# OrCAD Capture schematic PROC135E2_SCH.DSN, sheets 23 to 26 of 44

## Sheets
23 23. CPSW RGMII_2 ETHERNET CONN.: size C; title: CPSW RMII_2 ETHERNET PHY
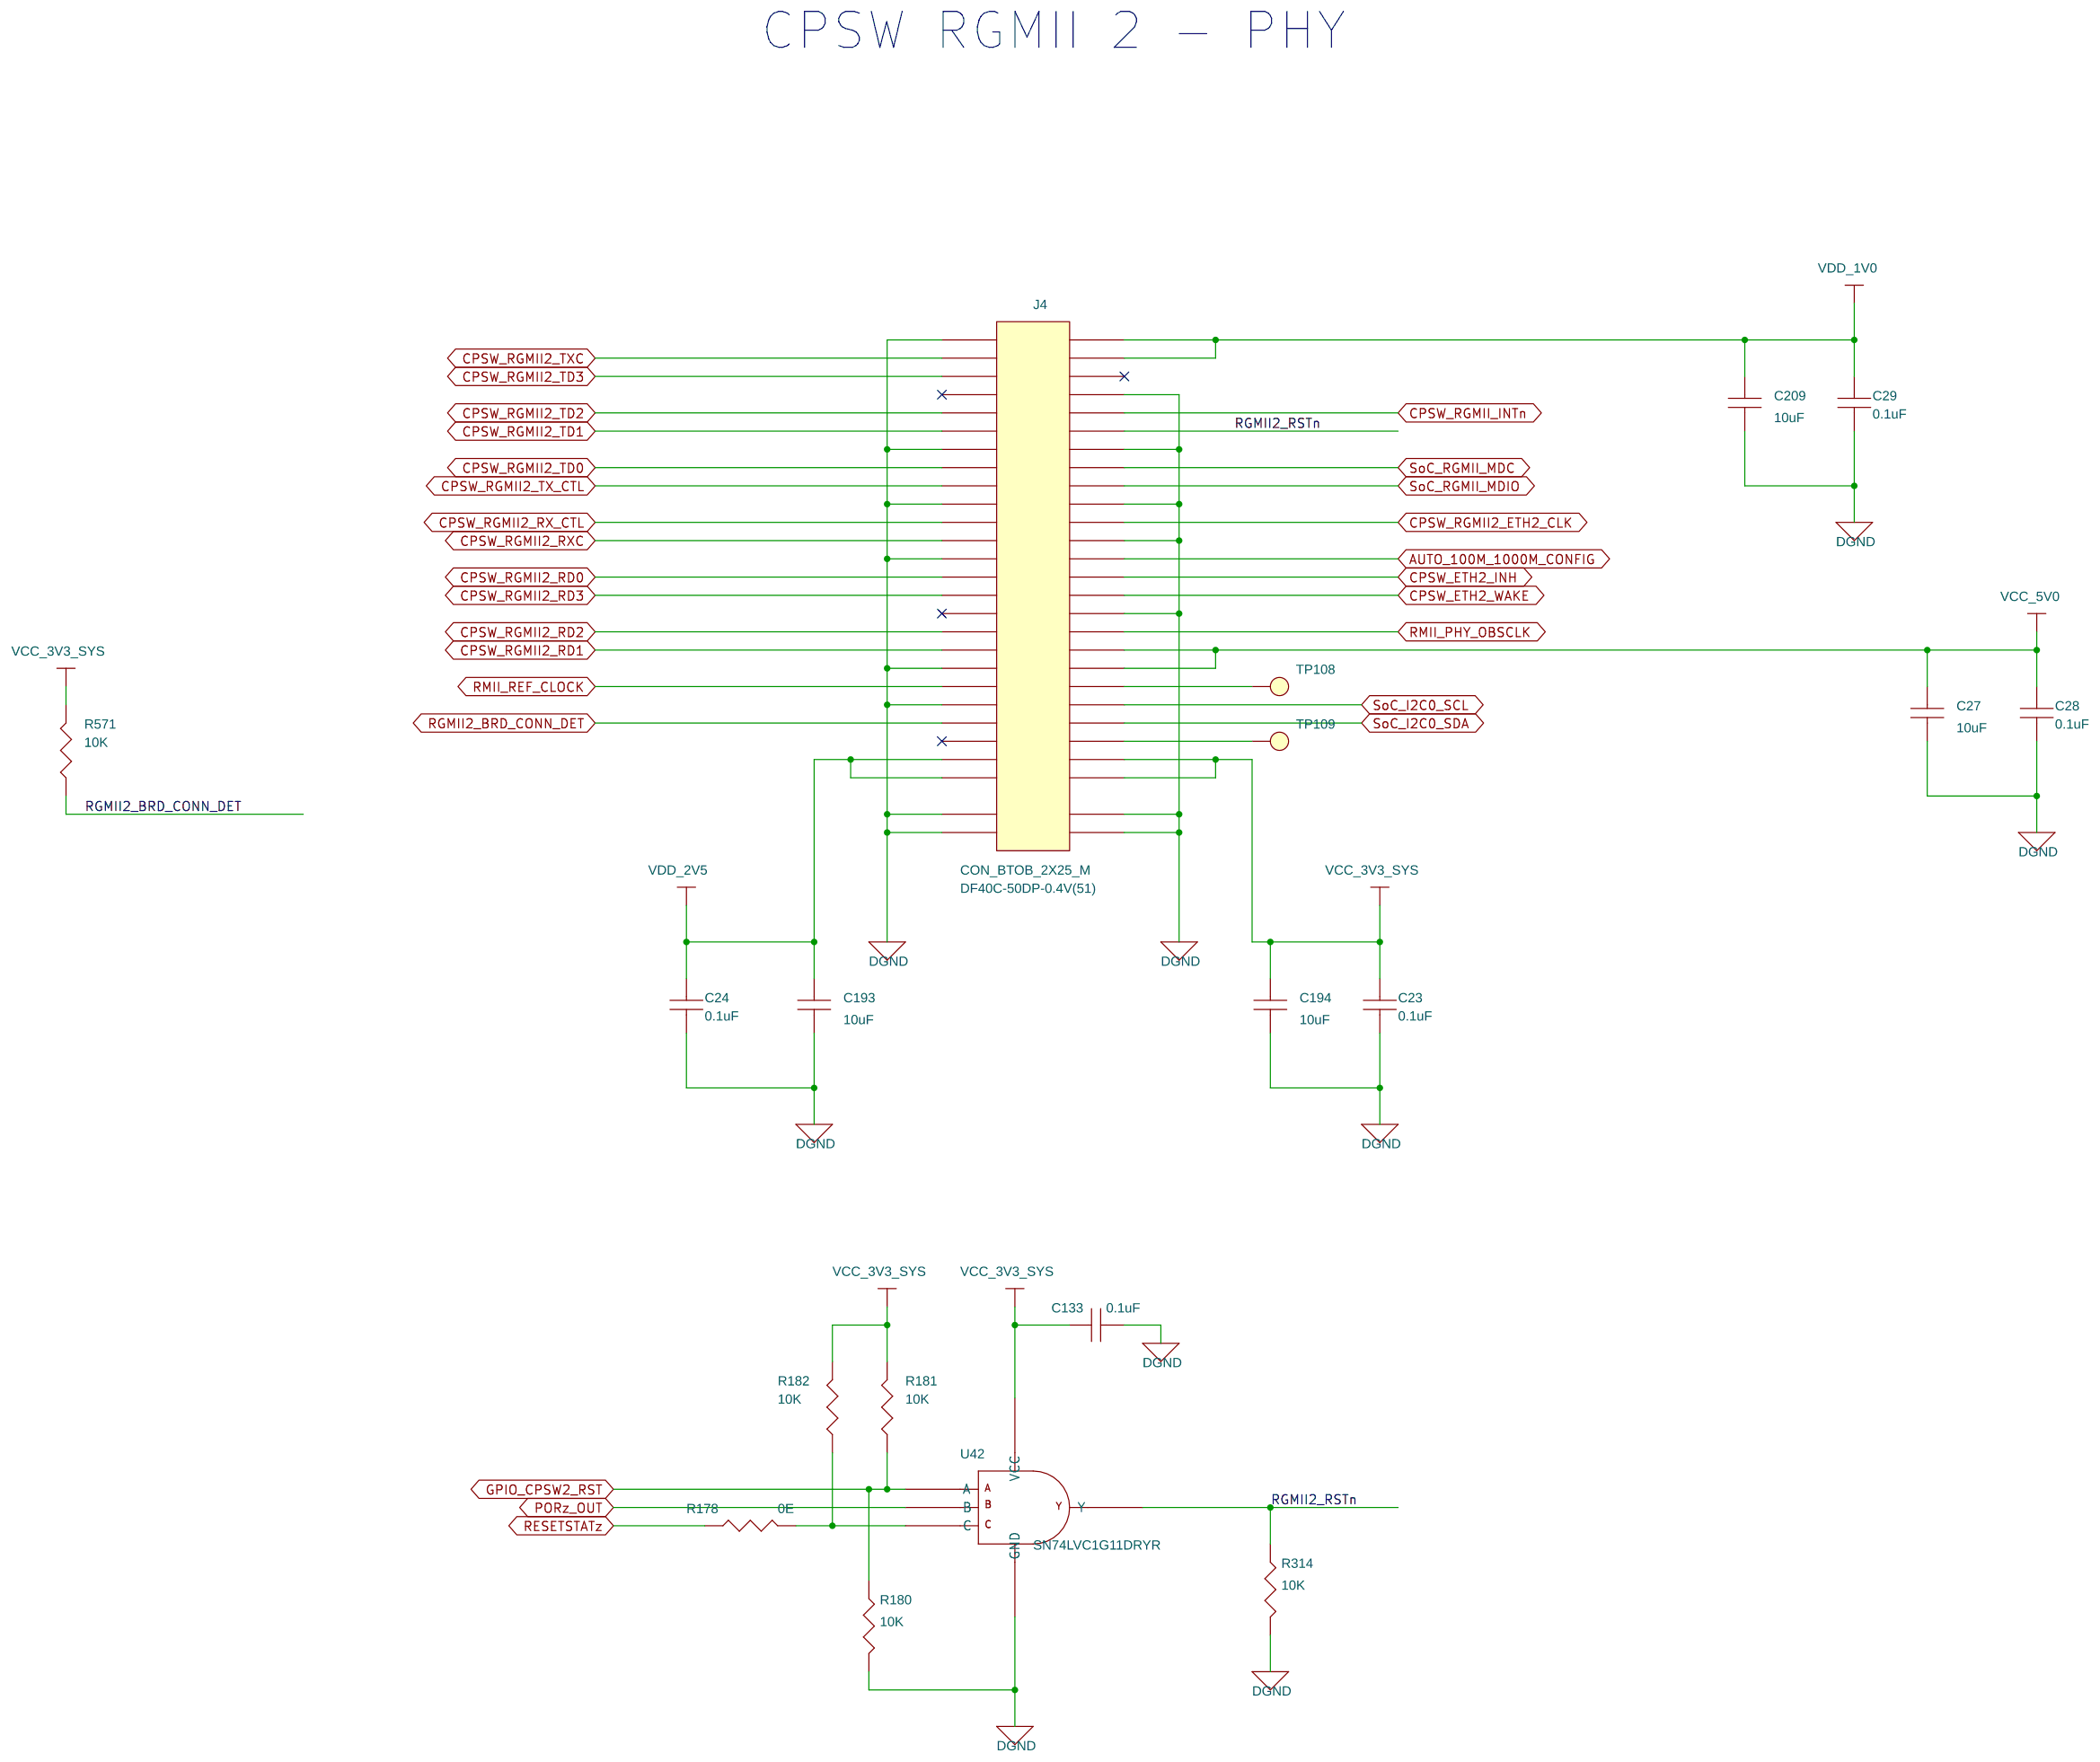
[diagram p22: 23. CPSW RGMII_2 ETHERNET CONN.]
24 24. PHY CLK & LED DRIVER: size C; title: ETHERNET PHY CLOCK BUFFER & LED DRIVER
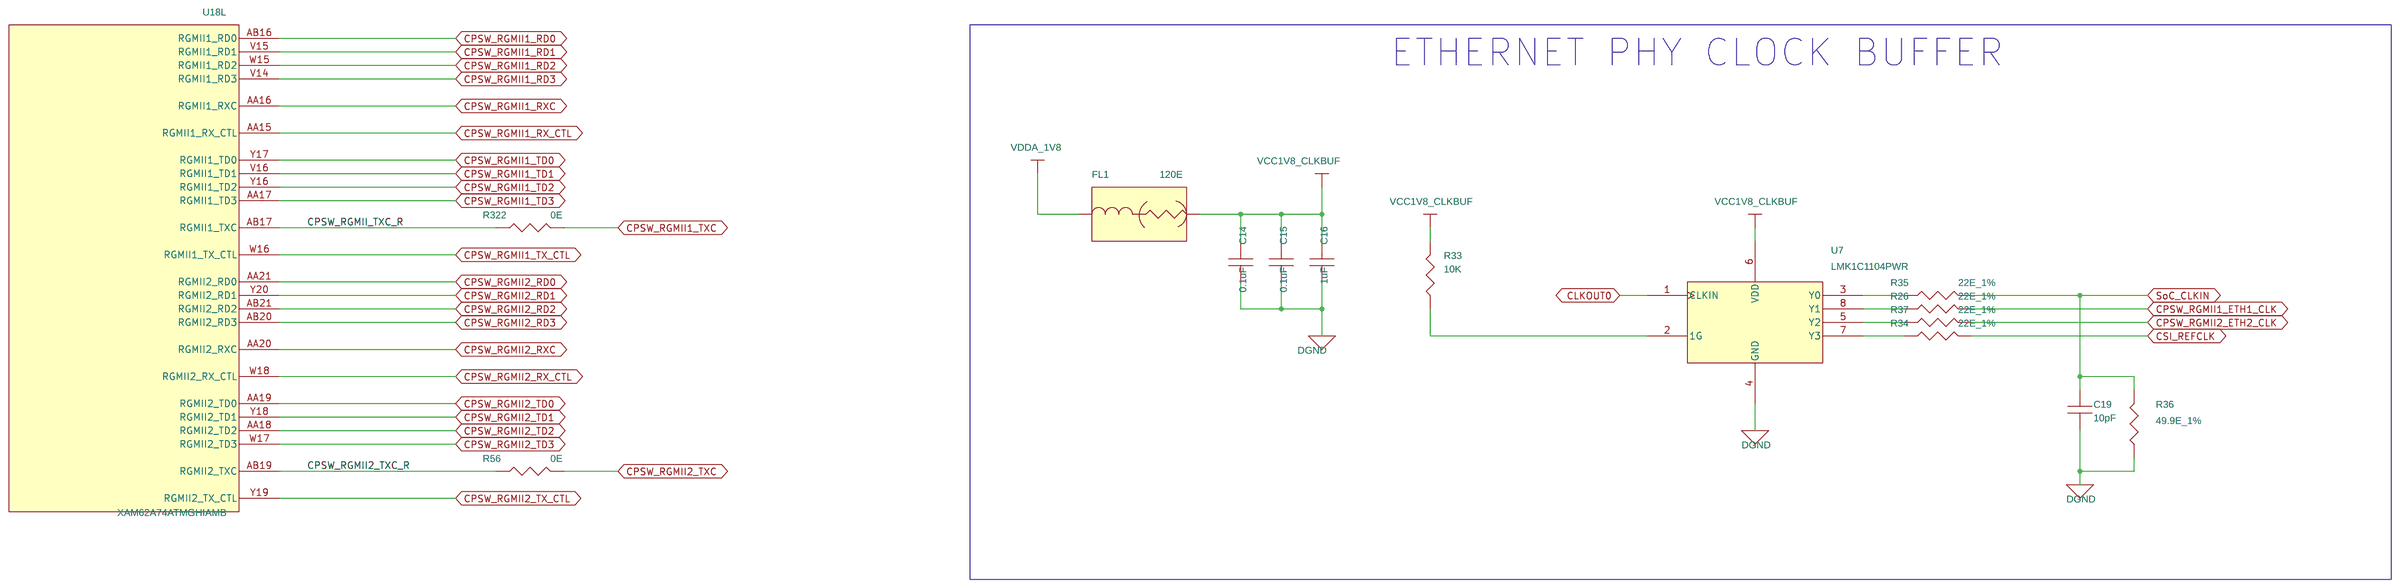
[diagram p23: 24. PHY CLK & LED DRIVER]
25 25. TEST AUTOMATION: size C; title: TEST AUTOMATION
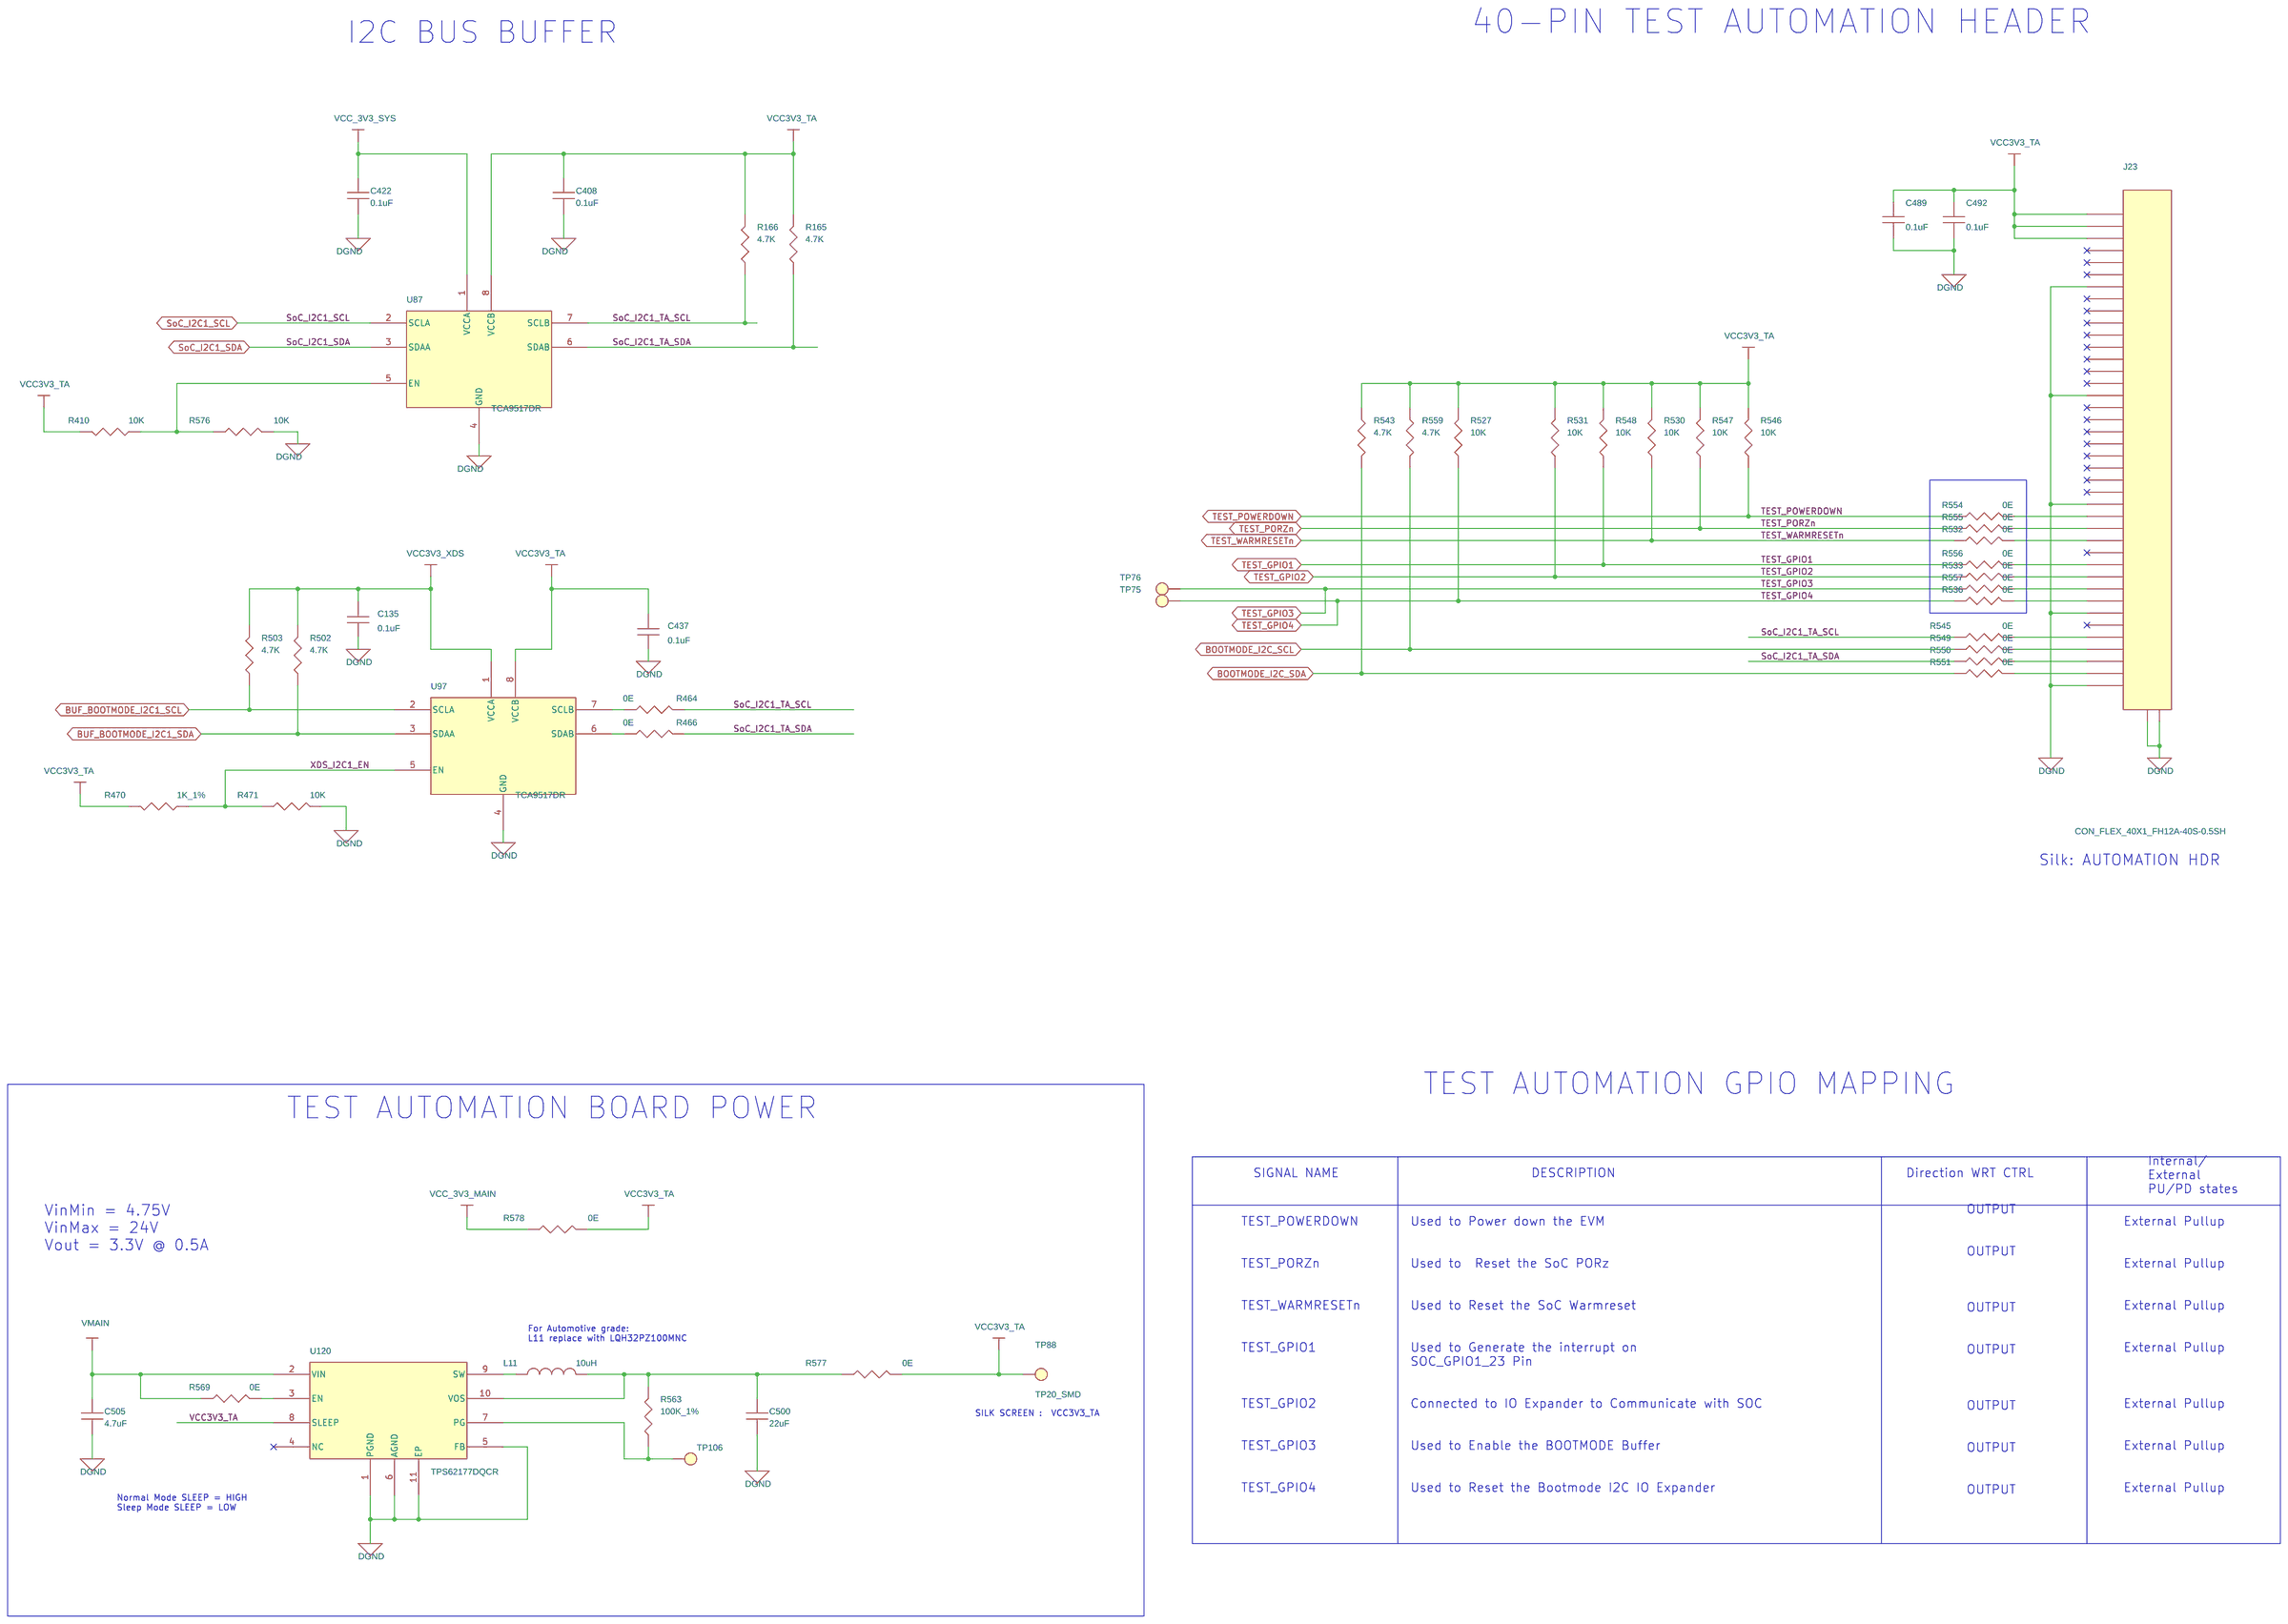
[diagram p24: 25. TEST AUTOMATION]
26 26. BOOT MODE BUFFER & SWITCHES: size C; title: BOOT MODE BUFFER & SWITCHES
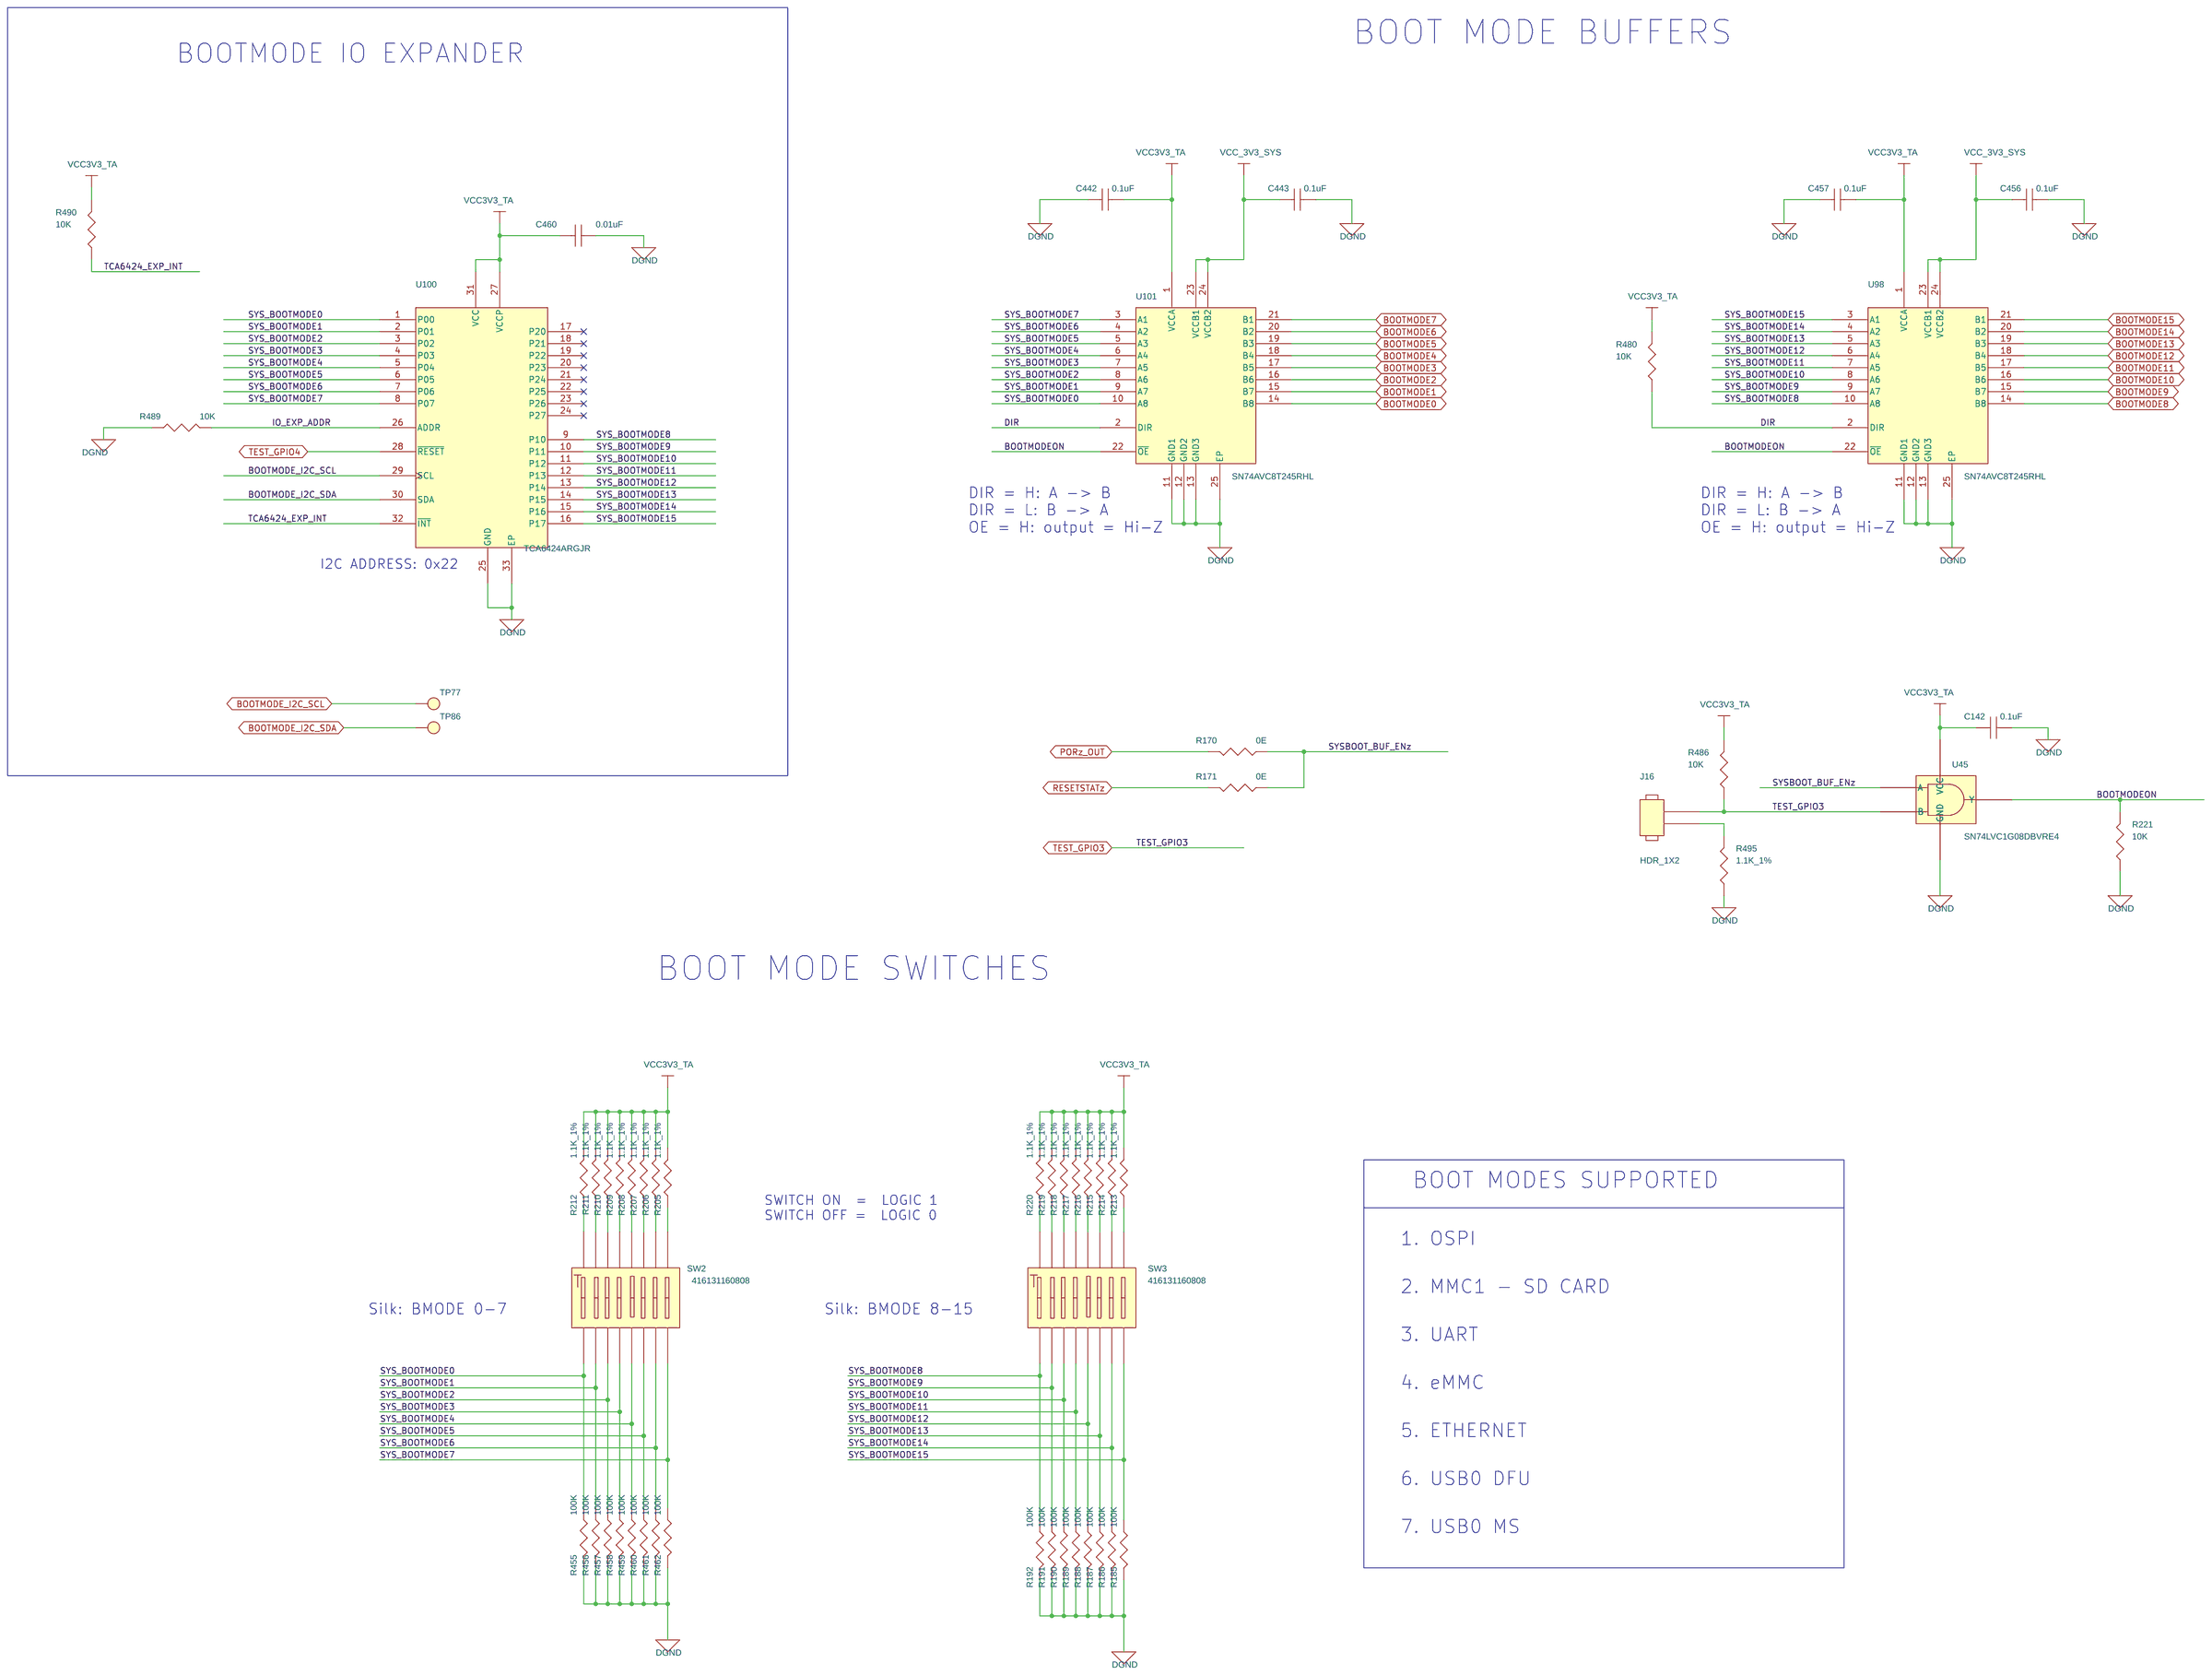
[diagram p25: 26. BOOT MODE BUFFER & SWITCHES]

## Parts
sheet 23. CPSW RGMII_2 ETHERNET CONN.
C23  0.1uF  [CAP0402_0-75]
C24  0.1uF  [CAP0402_0-75]
C27  10uF  [CAP0402_0-75]
C28  0.1uF  [CAP0402_0-75]
C29  0.1uF  [CAP0402_0-75]
C133  0.1uF  [CAP0201_0-5]
C193  10uF  [CAP0402_0-75]
C194  10uF  [CAP0402_0-75]
C209  10uF  [CAP0402_0-75]
J4  CON_BTOB_2X25_M  [CON_BTOB2X25_DF40C-50DP_P_S_S_1-3]
R178  0E  [RES0201_0-5]
R180  10K  [RES0201_0-5]
R181  10K  [RES0201_0-5]
R182  10K  [RES0201_0-5]
R314  10K  [RES0201_0-5]
R571  10K  [RES0201_0-5]
TP108  TP30_SMD  [TP30_SMD]
TP109  TP30_SMD  [TP30_SMD]
U42  SN74LVC1G11DRYR  [SON6_SN74LVC2G17_40X60_0-6]
sheet 24. PHY CLK & LED DRIVER
C14  0.1uF  [CAP0201_0-5]
C15  0.1uF  [CAP0201_0-5]
C16  1uF  [CAP0201_0-5]
C19  10pF  [CAP0201_0-5]
FL1  120E  [EMIFIL_BLM15A_0402_0-6]
R26  22E_1%  [RES0201_0-5]
R33  10K  [RES0201_0-5]
R34  22E_1%  [RES0201_0-5]
R35  22E_1%  [RES0201_0-5]
R36  49.9E_1%  [RES0402_0-5]
R37  22E_1%  [RES0201_0-5]
R56  0E  [RES0201_0-5]
R322  0E  [RES0201_0-5]
U7  LMK1C1104PWR  [TSSOP8_25-59_125X180_1-2]
sheet 25. TEST AUTOMATION
C135  0.1uF  [CAP0201_0-5]
C408  0.1uF  [CAP0201_0-5]
C422  0.1uF  [CAP0201_0-5]
C437  0.1uF  [CAP0201_0-5]
C489  0.1uF  [CAP0201_0-5]
C492  0.1uF  [CAP0201_0-5]
C500  22uF  [CAP0603_1]
C505  4.7uF  [CAP0603_1]
J23  CON_FLEX_40X1_FH12A-40S-0.5SH  [CON_FLEX40X1_FH12A_S_R_S]
L11  10uH  [IND_1277AS-H_130X110_SMD_1-2]
R165  4.7K  [RES0201_0-5]
R166  4.7K  [RES0201_0-5]
R410  10K  [RES0201_0-5]
R464  0E  [RES0201_0-5]
R466  0E  [RES0201_0-5]
R470  1K_1%  [RES0402_0-5]
R471  10K  [RES0201_0-5]
R502  4.7K  [RES0201_0-5]
R503  4.7K  [RES0201_0-5]
R527  10K  [RES0201_0-5]
R530  10K  [RES0201_0-5]
R531  10K  [RES0201_0-5]
R532  0E  [RES0201_0-5]
R533  0E  [RES0201_0-5]
R536  0E  [RES0201_0-5]
R543  4.7K  [RES0201_0-5]
R545  0E  [RES0201_0-5]
R546  10K  [RES0201_0-5]
R547  10K  [RES0201_0-5]
R548  10K  [RES0201_0-5]
R549  0E  [RES0201_0-5]
R550  0E  [RES0201_0-5]
R551  0E  [RES0201_0-5]
R554  0E  [RES0201_0-5]
R555  0E  [RES0201_0-5]
R556  0E  [RES0201_0-5]
R557  0E  [RES0201_0-5]
R559  4.7K  [RES0201_0-5]
R563  100K_1%  [RES0402_0-5]
R569  0E  [RES0402_0-5]
R576  10K  [RES0201_0-5]
R577  0E  [RES0805_0-75]
R578  0E  [RES0805_0-75]
TP75  TP20_SMD  [TP20_SMD]
TP76  TP20_SMD  [TP20_SMD]
TP88  TP20_SMD  [TP20_SMD]
TP106  TP20_SMD  [TP20_SMD]
U87  TCA9517DR  [SOIC8_1-8]
U97  TCA9517DR  [SOIC8_1-8]
U120  TPS62177DQCR  [WSON10_19-68_80X120_0-8]
sheet 26. BOOT MODE BUFFER & SWITCHES
C142  0.1uF  [CAP0201_0-5]
C442  0.1uF  [CAP0201_0-5]
C443  0.1uF  [CAP0201_0-5]
C456  0.1uF  [CAP0201_0-5]
C457  0.1uF  [CAP0201_0-5]
C460  0.01uF  [CAP0201_0-5]
J16  HDR_1X2  [HDR_1X2_90120-0122_S_T_5-6]
R170  0E  [RES0201_0-5]
R171  0E  [RES0201_0-5]
R185  100K  [RES0201_0-5]
R186  100K  [RES0201_0-5]
R187  100K  [RES0201_0-5]
R188  100K  [RES0201_0-5]
R189  100K  [RES0201_0-5]
R190  100K  [RES0201_0-5]
R191  100K  [RES0201_0-5]
R192  100K  [RES0201_0-5]
R205  1.1K_1%  [RES0201_0-5]
R206  1.1K_1%  [RES0201_0-5]
R207  1.1K_1%  [RES0201_0-5]
R208  1.1K_1%  [RES0201_0-5]
R209  1.1K_1%  [RES0201_0-5]
R210  1.1K_1%  [RES0201_0-5]
R211  1.1K_1%  [RES0201_0-5]
R212  1.1K_1%  [RES0201_0-5]
R213  1.1K_1%  [RES0201_0-5]
R214  1.1K_1%  [RES0201_0-5]
R215  1.1K_1%  [RES0201_0-5]
R216  1.1K_1%  [RES0201_0-5]
R217  1.1K_1%  [RES0201_0-5]
R218  1.1K_1%  [RES0201_0-5]
R219  1.1K_1%  [RES0201_0-5]
R220  1.1K_1%  [RES0201_0-5]
R221  10K  [RES0201_0-5]
R455  100K  [RES0201_0-5]
R456  100K  [RES0201_0-5]
R457  100K  [RES0201_0-5]
R458  100K  [RES0201_0-5]
R459  100K  [RES0201_0-5]
R460  100K  [RES0201_0-5]
R461  100K  [RES0201_0-5]
R462  100K  [RES0201_0-5]
R480  10K  [RES0201_0-5]
R486  10K  [RES0201_0-5]
R489  10K  [RES0201_0-5]
R490  10K  [RES0201_0-5]
R495  1.1K_1%  [RES0201_0-5]
SW2  416131160808  [SW16_416131160808_460X230_SMD_2-7]
SW3  416131160808  [SW16_416131160808_460X230_SMD_2-7]
TP77  TP20_SMD  [TP20_SMD]
TP86  TP20_SMD  [TP20_SMD]
U45  SN74LVC1G08DBVRE4  [SOT23-5]
U98  SN74AVC8T245RHL  [QFN24_19-68_220X140_1]
U100  TCA6424ARGJR  [QFN32_19-68_200X200]
U101  SN74AVC8T245RHL  [QFN24_19-68_220X140_1]
sheet 31. SOC WKUP & GPMC
U18  XAM62A74ATMGHIAMB  [FBGA484_31-49_710X710_2-7]  (sections A,B,C,D,E,F,G,H,I,J,K,L,M,N,O,P,Q)

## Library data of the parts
C23 C24 C28 C29 = CAP: CAP CERAMIC 0.1uF 50V 10% X7R 0402; Chkd/date: MANIRAJA/261020; Crtd /date: ALVY/211020; Custom_Duty: 15%; Customs_HS_Code: 85322990; Distributor_name: DIGIKEY; Distributor_part_number: 490-10700-1-ND; Footprint Path: Y:\MIS_DATABASE\Library\ALTIUM_TOOL\PCB_FOOTPRINTS\Altium_Footprint_Lib.PcbLib; Height: 0.55MM; Library Path: Y:\MIS_DATABASE\Library\ALTIUM_TOOL\SCHEMATICS_PARTS\MS_DISCRETE_Library.schlib; Mfr_name: MURATA; Mfr_part_number: GRM155R71H104KE14D; Mistral Part No: 120011100014-R; Package: 0402; Part_type: CAPACITORS\CERAMIC; Project: J7_CP; RoHS: RoHS; Temperature: -55°C+125°C; Tolerance: 10%; Voltage: 50V; Wattage: NA; Weight: 3.1mg; Datasheet: Y:\MIS_DATABASE\DATASHEETS\CAPACITORS\GRM155R71H104KE14.PDF
C27 C193 C194 C209 = CAP: CAP CERAMIC 10uF 10V 20% X5R 0402; Chkd/date: MANIRAJA/300520; Crtd /date: ALVY/260520; Custom_Duty: 15%; Customs_HS_Code: 85322990; Distributor_name: DIGIKEY; Distributor_part_number: 490-GRM155R61A106ME11DTR-ND; Footprint Path: Y:\MIS_DATABASE\Library\ALTIUM_TOOL\PCB_FOOTPRINTS\Altium_Footprint_Lib.PcbLib; Height: 0.55MM; Library Path: Y:\MIS_DATABASE\Library\ALTIUM_TOOL\SCHEMATICS_PARTS\MS_DISCRETE_Library.schlib; Mfr_name: MURATA; Mfr_part_number: GRM155R61A106ME11D; Mistral Part No: 120013110019-R; Package: 0402; Part_type: CAPACITORS\CERAMIC; Project: QCS610_NANOSOM; RoHS: RoHS; Temperature: -55°C+85°C; Tolerance: 20%; Voltage: 10V; Wattage: NA; Weight: 3.1mg; Datasheet: Y:\MIS_DATABASE\DATASHEETS\CAPACITORS\MURATA-GXX-SER_NOV17.PDF
C14 C15 C133 C135 C142 C408 C422 C437 C442 C443 C456 C457 C489 C492 = CAP: CAP CERAMIC 0.1uF 16V 10% X5R 0201; Alt_Mfr_name: YAGEO AMERICA; Alt_Mfr_part_number: CC0402KRX5R8BB104; Chkd/date: MANIRAJA/230118; Crtd /date: MANIRAJA/230118; Custom_Duty: 15%; Customs_HS_Code: 85322990; Distributor_name: DIGIKEY; Distributor_part_number: 490-14305-1-ND; Footprint Path: Y:\MIS_DATABASE\Library\ALTIUM_TOOL\PCB_FOOTPRINTS\Altium_Footprint_Lib.PcbLib; Height: 0.33MM; Library Path: Y:\MIS_DATABASE\Library\ALTIUM_TOOL\SCHEMATICS_PARTS\MS_DISCRETE_Library.schlib; Mfr_name: MURATA; Mfr_part_number: GRM033R61C104KE14D; Mistral Part No: 120009030072-R; Package: 0201; Part_type: CAPACITORS\CERAMIC; Project: TI_MAXIE_CPB; RoHS: RoHS; Temperature: -55°C+85°C; Tolerance: 10%; Voltage: 16V; Wattage: NA; Weight: 0.33mg; Datasheet: Y:\MIS_DATABASE\DATASHEETS\CAPACITORS\GRM033R61C104KE14.PDF
J4 = CON_BTOB_25X2_M_4SH: CON BTOB 2X25 0.40MM PITCH MALE ST SMD; Chkd/date: MANIRAJA/291018; Crtd /date: ALVY/291018; Custom_Duty: 24%; Customs_HS_Code: 85369090; Distributor_name: DIGIKEY; Distributor_part_number: H11626CT-ND; Footprint Path: Y:\MIS_DATABASE\Library\ALTIUM_TOOL\PCB_FOOTPRINTS\Altium_Footprint_Lib.PcbLib; Height: 1.29MM; Library Path: Y:\MIS_DATABASE\Library\ALTIUM_TOOL\SCHEMATICS_PARTS\MS_CONNECTOR_Library.schlib; Mfr_name: HRS; Mfr_part_number: DF40C-50DP-0.4V(51); Mistral Part No: 150018100052-R; Package: SMD; Part_type: CONNECTOR\BTOB; Project: SD820_SHASTA_AB; RoHS: RoHS; Temperature: -35°C+85°C; Tolerance: NA; Voltage: NA; Wattage: NA; Weight: 38mg; Datasheet: Y:\MIS_DATABASE\DATASHEETS\CONNECTORS\DF40C-40DP.PDF
R170 R171 R178 R464 R466 R532 R533 R536 R545 R549-R551 R554-R557 = RESISTOR: RES 0E 1/20W 5% 0201; Chkd/date: NAVEED/301214; Crtd /date: MUDDU/120710; Custom_Duty: 15%; Customs_HS_Code: 85332119; Distributor_name: DIGIKEY; Distributor_part_number: 311-0.0NCT-ND; Footprint Path: Y:\MIS_DATABASE\Library\ALTIUM_TOOL\PCB_FOOTPRINTS\Altium_Footprint_Lib.PcbLib; Height: 0.26MM; Library Path: Y:\MIS_DATABASE\Library\ALTIUM_TOOL\SCHEMATICS_PARTS\MS_DISCRETE_Library.schlib; Mfr_name: YAGEO AMERICA; Mfr_part_number: RC0201JR-070RL; Mistral Part No: 110010070067-R; Package: 0201; Part_type: RESISTORS\FIXED; Project: PB_BUGBASE; RoHS: RoHS; Temperature: -55°C+125°C; Tolerance: 5%; Voltage: NA; Wattage: 1/20W; Weight: 0.17mg; Datasheet: Y:\MIS_DATABASE\DATASHEETS\RESISTORS\RCXXXXL-SER_MAR18.PDF
R33 R180-R182 R221 R314 R410 R471 R480 R486 R489 R490 R527 R530 R531 R546-R548 R571 R576 = RESISTOR: RES 10K 1/20W 5% 0201; Chkd/date: MANIRAJA/050517; Crtd /date: MANIRAJA/050517; Custom_Duty: 15%; Customs_HS_Code: 85332119; Distributor_name: DIGIKEY; Distributor_part_number: 311-10KNCT-ND; Footprint Path: Y:\MIS_DATABASE\Library\ALTIUM_TOOL\PCB_FOOTPRINTS\Altium_Footprint_Lib.PcbLib; Height: 0.26MM; Library Path: Y:\MIS_DATABASE\Library\ALTIUM_TOOL\SCHEMATICS_PARTS\MS_DISCRETE_Library.schlib; Mfr_name: YAGEO AMERICA; Mfr_part_number: RC0201JR-0710KL; Mistral Part No: 110010070051-R; Package: 0201; Part_type: RESISTORS\FIXED; Project: GOLDEN-I LITE; RoHS: RoHS; Temperature: -55°C+125°C; Tolerance: 5%; Voltage: NA; Wattage: 1/20W; Weight: 0.17mg; Datasheet: Y:\MIS_DATABASE\DATASHEETS\RESISTORS\RCXXXXL-SER_MAR18.PDF
TP108 TP109 = TESTPOINT: TESTPOINT CIR 30 SMD; Chkd/date: SHREESHAIL/171006; Crtd /date: MAZHAR/171006; Custom_Duty: NA; Customs_HS_Code: NA; Distributor_name: NA; Distributor_part_number: NA; Footprint Path: Y:\MIS_DATABASE\Library\ALTIUM_TOOL\PCB_FOOTPRINTS\Altium_Footprint_Lib.PcbLib; Height: NA; Library Path: Y:\MIS_DATABASE\Library\ALTIUM_TOOL\SCHEMATICS_PARTS\MS_DISCRETE_Library.schlib; MECHANICAL 3D STEP FILE: NA; Mfr_name: LOCAL; Mistral Part No: 130009030930; Package: SMD; Project: BT MODULE_CSRBC04; RoHS: NA; Temperature: NA; Tolerance: NA; Voltage: NA; Wattage: NA; Weight: NA; Datasheet: NA
U42 = SN74LVC1G11DCKR_SC70-6: IC SINGLE 3-INPUT POSITIVE-AND GATE SON6; Chkd/date: MANIRAJA/270121; Crtd /date: ALVY/270121; Custom_Duty: 15%; Customs_HS_Code: 85423100; Distributor_name: DIGIKEY; Distributor_part_number: 296-30120-1-ND; Footprint Path: Y:\MIS_DATABASE\Library\ALTIUM_TOOL\PCB_FOOTPRINTS\Altium_Footprint_Lib.PcbLib; Height: 0.60MM; Library Path: Y:\MIS_DATABASE\Library\ALTIUM_TOOL\SCHEMATICS_PARTS\MS_GATE_Library.schlib; Mfr_name: TEXAS INSTRUMENTS; Mistral Part No: 141021010013-R; Package: SON6; Part_type: ICS\DIGITAL\GATES; Project: AM64X_SKEVM; RoHS: RoHS; Temperature: -40°C+125°C; Tolerance: NA; Voltage: NA; Wattage: NA; Weight: 33mg; Datasheet: Y:\MIS_DATABASE\DATASHEETS\ICS\DIGITAL\GATES\SN74LVC1G_NOV16.PDF
C16 = CAP: CAP CERAMIC 1uF 16V 20% X5R 0201; Chkd/date: MANIRAJA/300520; Crtd /date: ALVY/260520; Custom_Duty: 15%; Customs_HS_Code: 85322990; Distributor_name: DIGIKEY; Distributor_part_number: 490-18654-1-ND; Footprint Path: Y:\MIS_DATABASE\Library\ALTIUM_TOOL\PCB_FOOTPRINTS\Altium_Footprint_Lib.PcbLib; Height: 0.39MM; Library Path: Y:\MIS_DATABASE\Library\ALTIUM_TOOL\SCHEMATICS_PARTS\MS_DISCRETE_Library.schlib; Mfr_name: MURATA; Mfr_part_number: GRM033R61C105ME15D; Mistral Part No: 120018090038-R; Package: 0201; Part_type: CAPACITORS\CERAMIC; Project: QCS610_NANOSOM; RoHS: RoHS; Temperature: -55°C+85°C; Tolerance: 20%; Voltage: 16V; Wattage: NA; Weight: 0.33mg; Datasheet: Y:\MIS_DATABASE\DATASHEETS\CAPACITORS\GRM033R61C105ME15.PDF
C19 = CAP: CAP CERAMIC 10pF 25V 5% HI-Q C0G(NP0) 0201; Chkd/date: VASANTHA/081216; Crtd /date: MANIRAJA/081216; Custom_Duty: 15%; Customs_HS_Code: 85322990; Distributor_name: DIGIKEY; Distributor_part_number: 490-13312-1-ND; Footprint Path: Y:\MIS_DATABASE\Library\ALTIUM_TOOL\PCB_FOOTPRINTS\Altium_Footprint_Lib.PcbLib; Height: 0.33MM; Library Path: Y:\MIS_DATABASE\Library\ALTIUM_TOOL\SCHEMATICS_PARTS\MS_DISCRETE_Library.schlib; Mfr_name: MURATA; Mfr_part_number: GJM0335C1E100JB01D; Mistral Part No: 120016120010-R; Package: 0201; Part_type: CAPACITORS\CERAMIC; Project: OCTBTS5200; RoHS: RoHS; Temperature: -55°C+125°C; Tolerance: 5%; Voltage: 25V; Wattage: NA; Weight: 0.33mg; Datasheet: Y:\MIS_DATABASE\DATASHEETS\CAPACITORS\MURATA-GXX-SER_NOV17.PDF
FL1 = EMIFILTER_IND: IND FERRITE BEAD CHIP 120E 2A 0402; Chkd/date: NAVEED/241114; Crtd /date: USMAN/170613; Custom_Duty: 24%; Customs_HS_Code: 85369090; Distributor_name: DIGIKEY; Distributor_part_number: 490-9656-1-ND; Footprint Path: Y:\MIS_DATABASE\Library\ALTIUM_TOOL\PCB_FOOTPRINTS\Altium_Footprint_Lib.PcbLib; Height: 0.55MM; Library Path: Y:\MIS_DATABASE\Library\ALTIUM_TOOL\SCHEMATICS_PARTS\MS_FILTER_Library.schlib; Mfr_name: MURATA; Mfr_part_number: BLM15PX121SN1D; Mistral Part No: 130013060022-R; Package: 0402; Part_type: INDUCTOR; Project: GEN_3-8; RoHS: RoHS; Temperature: -55°C+125°C; Tolerance: 25%; Voltage: NA; Wattage: NA; Weight: 1mg; Datasheet: Y:\MIS_DATABASE\DATASHEETS\DISCRETES\INDUCTORS\BLM15-SN1-SER.PDF
R26 R34 R35 R37 = RESISTOR: RES 22E 1/20W 1% 0201; Chkd/date: MANIRAJA/080319; Crtd /date: ALVY/080319; Custom_Duty: 15%; Customs_HS_Code: 85332119; Distributor_name: DIGIKEY; Distributor_part_number: YAG2518CT-ND; Footprint Path: Y:\MIS_DATABASE\Library\ALTIUM_TOOL\PCB_FOOTPRINTS\Altium_Footprint_Lib.PcbLib; Height: 0.26MM; Library Path: Y:\MIS_DATABASE\Library\ALTIUM_TOOL\SCHEMATICS_PARTS\MS_DISCRETE_Library.schlib; Mfr_name: YAGEO AMERICA; Mfr_part_number: RC0201FR-0722RL; Mistral Part No: 110009030522-R; Package: 0201; Part_type: RESISTORS\FIXED; Project: AM654x_SOM; RoHS: RoHS; Temperature: -55°C+125°C; Tolerance: 1%; Voltage: NA; Wattage: 1/20W; Weight: 0.17mg; Datasheet: Y:\MIS_DATABASE\DATASHEETS\RESISTORS\RCXXXXL-SER_MAR18.PDF
R36 = RESISTOR: RES 49.9E 1/16W 1% 0402; Chkd/date: MANIRAJA/210519; Crtd /date: MANIRAJA/210519; Custom_Duty: 15%; Customs_HS_Code: 85332119; Distributor_name: DIGIKEY; Distributor_part_number: 541-3967-1-ND; Footprint Path: Y:\MIS_DATABASE\Library\ALTIUM_TOOL\PCB_FOOTPRINTS\Altium_Footprint_Lib.PcbLib; Height: 0.35MM; Library Path: Y:\MIS_DATABASE\Library\ALTIUM_TOOL\SCHEMATICS_PARTS\MS_DISCRETE_Library.schlib; Mfr_name: VISHAY; Mfr_part_number: CRCW040249R9FKEDC; Mistral Part No: 110009030846-R; Package: 0402; Part_type: RESISTORS\FIXED; Project: RFSU_RFTJ_CARD; RoHS: RoHS; Temperature: -55°C+155°C; Tolerance: 1%; Voltage: NA; Wattage: 1/16W; Weight: 0.65mg; Datasheet: Y:\MIS_DATABASE\DATASHEETS\RESISTORS\CRCW_C-SER.PDF
R56 R322 = RESISTOR: RES 0E 1/20W 5% 0201; Chkd/date: NAVEED/301214; Crtd /date: MUDDU/120710; Custom_Duty: 15%; Customs_HS_Code: 85332119; Distributor_name: DIGIKEY; Distributor_part_number: 311-0.0NCT-ND; Footprint Path: Y:\MIS_DATABASE\Library\ALTIUM_TOOL\PCB_FOOTPRINTS\Altium_Footprint_Lib.PcbLib; Height: 0.26MM; Library Path: Y:\MIS_DATABASE\Library\ALTIUM_TOOL\SCHEMATICS_PARTS\MS_DISCRETE_Library.schlib; Mfr_name: YAGEO AMERICA; Mfr_part_number: RC0201JR-070RL; Mistral Part No: 110010070067-R; Package: 0201; Part_type: RESISTORS\FIXED; Project: PB_BUGBASE; RoHS: RoHS; SIGNAL_MODEL: RESISTOR_RES0201_0-5_0E_0E; Temperature: -55°C+125°C; Tolerance: 5%; Voltage: NA; Wattage: 1/20W; Weight: 0.17mg; Datasheet: Y:\MIS_DATABASE\DATASHEETS\RESISTORS\RCXXXXL-SER_MAR18.PDF
U7 = LMK1C1104_TSSOP8: IC LVCMOS CLOCK BUFFER TSSOP8; Chkd/date: MANIRAJA/190520; Crtd /date: ALVY/190520; Custom_Duty: 15%; Customs_HS_Code: 85423100; Distributor_name: DIGIKEY; Distributor_part_number: 296-LMK1C1104PWRCT-ND; Footprint Path: Y:\MIS_DATABASE\Library\ALTIUM_TOOL\PCB_FOOTPRINTS\Altium_Footprint_Lib.PcbLib; Height: 1.20MM; Library Path: Y:\MIS_DATABASE\Library\ALTIUM_TOOL\SCHEMATICS_PARTS\MS_COMBINATIONAL_Library.schlib; Manufacturer: TEXAS INSTRUMENTS; Mfr_name: TEXAS INSTRUMENTS; Mistral Part No: 141020050011-R; Package: TSSOP8; Part_type: ICS\DIGITAL\COMBINATIONAL; Project: RETROFIT-RAD2; RoHS: RoHS; Temperature: -40°C+125°C; Tolerance: NA; Voltage: NA; Wattage: NA; Weight: 34.2mg; Datasheet: Y:\MIS_DATABASE\DATASHEETS\ICS\DIGITAL\COMBINATIONAL\LMK1C1104.PDF
C500 = CAP: CAP CERAMIC 22uF 10V 20% X5R 0603; Chkd/date: MANIRAJA/230118; Crtd /date: MANIRAJA/230118; Custom_Duty: 15%; Customs_HS_Code: 85322990; Distributor_name: DIGIKEY; Distributor_part_number: 490-10476-1-ND; Footprint Path: Y:\MIS_DATABASE\Library\ALTIUM_TOOL\PCB_FOOTPRINTS\Altium_Footprint_Lib.PcbLib; Height: 1.00MM; Library Path: Y:\MIS_DATABASE\Library\ALTIUM_TOOL\SCHEMATICS_PARTS\MS_DISCRETE_Library.schlib; Mfr_name: MURATA; Mfr_part_number: GRM188R61A226ME15D; Mistral Part No: 120014100009-R; Package: 0603; Part_type: CAPACITORS\CERAMIC; Project: TI_MAXIE_CPB; RoHS: RoHS; Temperature: -55°C+85°C; Tolerance: 20%; Voltage: 10V; Wattage: NA; Weight: 6.3mg; Datasheet: Y:\MIS_DATABASE\DATASHEETS\CAPACITORS\GRM188R61A226ME15.PDF
C505 = CAP: CAP CERAMIC 4.7uF 35V 20% X5R 0603; Chkd/date: MANIRAJA/120520; Crtd /date: ALVY/120520; Custom_Duty: 15%; Customs_HS_Code: 85322990; Distributor_name: DIGIKEY; Distributor_part_number: 490-11995-1-ND; Footprint Path: Y:\MIS_DATABASE\Library\ALTIUM_TOOL\PCB_FOOTPRINTS\Altium_Footprint_Lib.PcbLib; Height: 1.00MM; Library Path: Y:\MIS_DATABASE\Library\ALTIUM_TOOL\SCHEMATICS_PARTS\MS_DISCRETE_Library.schlib; Mfr_name: MURATA; Mfr_part_number: GRM188R6YA475ME15D; Mistral Part No: 120020050017-R; Package: 0603; Part_type: CAPACITORS\CERAMIC; Project: SD865_NANOSOM; RoHS: RoHS; Temperature: -55°C+85°C; Tolerance: 20%; Voltage: 35V; Wattage: NA; Weight: 6.3mg; Datasheet: Y:\MIS_DATABASE\DATASHEETS\CAPACITORS\GRM188R6YA475ME15.PDF
J23 = CON_FLEX_40X1_FH12A-40S-0.5SH: CON FPC 40X1 0.50MM PITCH RT TOP SMD; Chkd/date: SHREESHAIL/201106; Crtd /date: MAZHAR/171106; Custom_Duty: 24%; Customs_HS_Code: 85369090; Distributor_name: DIGIKEY; Distributor_part_number: HFK40CT-ND; Height: 2.00MM; Mfr_name: HIROSE ELECTRIC EUROPE; Mfr_part_number: FH12A-40S-0.5SH(55); Mistral Part No: 150009030176-R; Package: SMD; Part_type: CONNECTOR\FPC; Project: PMP LCD BOARD; Datasheet: Y:\MIS_DATABASE\DATASHEETS\CONNECTORS\FH12SERIES.PDF
L11 = INDUCTOR: IND POWER 10uH 900mA 20% SMD; Chkd/date: MANIRAJA/200921; Crtd /date: ALVY/200921; Custom_Duty: 24%; Customs_HS_Code: 85369090; Distributor_name: DIGIKEY; Distributor_part_number: 490-10589-1-ND; Footprint Path: Y:\MIS_DATABASE\Library\ALTIUM_TOOL\PCB_FOOTPRINTS\Altium_Footprint_Lib.PcbLib; Height: 1.20MM; Library Path: Y:\MIS_DATABASE\Library\ALTIUM_TOOL\SCHEMATICS_PARTS\MS_DISCRETE_Library.schlib; Mfr_name: MURATA; Mfr_part_number: 1277AS-H-100M=P2; Mistral Part No: 130021090022-R; Package: SMD; Project: TI_AM62x SKEVM_BRD; RoHS: RoHS; Temperature: -40°C+85°C; Tolerance: 20%; Voltage: NA; Wattage: NA; Weight: NA; Datasheet: Y:\MIS_DATABASE\DATASHEETS\DISCRETES\INDUCTORS\MURATA-1277AS-H.PDF
R165 R166 R502 R503 R543 R559 = RESISTOR: RES 4.7K 1/20W 5% 0201; Chkd/date: MANIRAJA/200921; Crtd /date: ALVY/200921; Custom_Duty: 15%; Customs_HS_Code: 85332119; Distributor_name: DIGIKEY; Distributor_part_number: 311-4.7KNCT-ND; Footprint Path: Y:\MIS_DATABASE\Library\ALTIUM_TOOL\PCB_FOOTPRINTS\Altium_Footprint_Lib.PcbLib; Height: 0.26MM; Library Path: Y:\MIS_DATABASE\Library\ALTIUM_TOOL\SCHEMATICS_PARTS\MS_DISCRETE_Library.schlib; Mfr_name: YAGEO AMERICA; Mfr_part_number: RC0201JR-074K7L; Mistral Part No: 110021090007-R; Package: 0201; Part_type: RESISTORS\FIXED; Project: TI_AM62x SKEVM_BRD; RoHS: RoHS; Temperature: -55°C+125°C; Tolerance: 5%; Voltage: NA; Wattage: 1/20W; Weight: 0.17mg; Datasheet: Y:\MIS_DATABASE\DATASHEETS\RESISTORS\RCXXXXL-SER_MAR18.PDF
R470 = RESISTOR: RES 1K 1/10W 1% 0402; Chkd/date: VASANTHA/281216; Crtd /date: MAZHAR/150506; Custom_Duty: 15%; Customs_HS_Code: 85332119; Distributor_name: DIGIKEY; Distributor_part_number: P1.00KLCT-ND; Footprint Path: Y:\MIS_DATABASE\Library\ALTIUM_TOOL\PCB_FOOTPRINTS\Altium_Footprint_Lib.PcbLib; Height: 0.40MM; Library Path: Y:\MIS_DATABASE\Library\ALTIUM_TOOL\SCHEMATICS_PARTS\MS_DISCRETE_Library.schlib; Mfr_name: PANASONIC-ECG; Mfr_part_number: ERJ-2RKF1001X; Mistral Part No: 110009030411-R; Package: 0402; Part_type: RESISTORS\FIXED; Project: VOCERA; RoHS: RoHS; Temperature: -55°C+155°C; Tolerance: 1%; Voltage: NA; Wattage: 1/10W; Weight: 0.8mg; Datasheet: Y:\MIS_DATABASE\DATASHEETS\RESISTORS\PAN-ERJSER_NOV17.PDF
R563 = RESISTOR: RES 100K 1/10W 1% 0402; Chkd/date: VASANTHA/201216; Crtd /date: MAZHAR/130306; Custom_Duty: 15%; Customs_HS_Code: 85332119; Distributor_name: DIGIKEY; Distributor_part_number: P100KLCT-ND; Footprint Path: Y:\MIS_DATABASE\Library\ALTIUM_TOOL\PCB_FOOTPRINTS\Altium_Footprint_Lib.PcbLib; Height: 0.40MM; Library Path: Y:\MIS_DATABASE\Library\ALTIUM_TOOL\SCHEMATICS_PARTS\MS_DISCRETE_Library.schlib; Mfr_name: PANASONIC-ECG; Mfr_part_number: ERJ-2RKF1003X; Mistral Part No: 110009030187-R; Package: 0402; Part_type: RESISTORS\FIXED; Project: J32; RoHS: RoHS; Temperature: -55°C+155°C; Tolerance: 1%; Voltage: NA; Wattage: 1/10W; Weight: 0.8mg; Datasheet: Y:\MIS_DATABASE\DATASHEETS\RESISTORS\PAN-ERJSER_NOV17.PDF
R569 = RESISTOR: RES 0E 1/16W JUMPER 0402; Chkd/date: VASANTHA/201216; Crtd /date: MUDDU/190810; Custom_Duty: 15%; Customs_HS_Code: 85332119; Distributor_name: DIGIKEY; Distributor_part_number: 541-0.0JCT-ND; Footprint Path: Y:\MIS_DATABASE\Library\ALTIUM_TOOL\PCB_FOOTPRINTS\Altium_Footprint_Lib.PcbLib; Height: 0.40MM; Library Path: Y:\MIS_DATABASE\Library\ALTIUM_TOOL\SCHEMATICS_PARTS\MS_DISCRETE_Library.schlib; Mfr_name: VISHAY; Mfr_part_number: CRCW04020000Z0ED; Mistral Part No: 110010080019-R; Package: 0402; Part_type: RESISTORS\FIXED; Project: PB_BUGBASE; RoHS: RoHS; Temperature: -55°C+155°C; Tolerance: NA; Voltage: NA; Wattage: 1/16W; Weight: 0.65mg; Datasheet: Y:\MIS_DATABASE\DATASHEETS\RESISTORS\CRCW0603.PDF
R577 R578 = RESISTOR: RES 0E 1/8W 5% 0805; Chkd/date: VASANTHA/130416; Crtd /date: JEBRAN/020316; Custom_Duty: 15%; Customs_HS_Code: 85332119; Distributor_name: DIGIKEY; Distributor_part_number: 311-0.0ARCT-ND; Footprint Path: Y:\MIS_DATABASE\Library\ALTIUM_TOOL\PCB_FOOTPRINTS\Altium_Footprint_Lib.PcbLib; Height: 0.60MM; Library Path: Y:\MIS_DATABASE\Library\ALTIUM_TOOL\SCHEMATICS_PARTS\MS_DISCRETE_Library.schlib; Mfr_name: YAGEO AMERICA; Mfr_part_number: RC0805JR-070RL; Mistral Part No: 110009030074-R; Package: 0805; Part_type: RESISTORS\FIXED; Project: ZK_BIOMETRIC; RoHS: RoHS; Temperature: -55°C+155°C; Tolerance: 5%; Voltage: NA; Wattage: 1/8W; Weight: 5.5mg; Datasheet: Y:\MIS_DATABASE\DATASHEETS\RESISTORS\RCXXXXL-SER_MAR18.PDF
TP75-TP77 TP86 TP106 = TESTPOINT: TESTPOINT CIR 20 SMD; Chkd/date: SHREESHAIL/171006; Crtd /date: MAZHAR/171006; Custom_Duty: NA; Customs_HS_Code: NA; Distributor_name: NA; Distributor_part_number: NA; Footprint Path: Y:\MIS_DATABASE\Library\ALTIUM_TOOL\PCB_FOOTPRINTS\Altium_Footprint_Lib.PcbLib; Height: NA; Library Path: Y:\MIS_DATABASE\Library\ALTIUM_TOOL\SCHEMATICS_PARTS\MS_DISCRETE_Library.schlib; MECHANICAL 3D STEP FILE: NA; Mfr_name: LOCAL; Mistral Part No: NA; Package: SMD; Project: BT MODULE_CSRBC04; RoHS: NA; Temperature: NA; Tolerance: NA; Voltage: NA; Wattage: NA; Weight: NA; Datasheet: NA
TP88 = TESTPOINT: TESTPOINT CIR 20 SMD; Chkd/date: SHREESHAIL/171006; Crtd /date: MAZHAR/171006; Custom_Duty: NA; Customs_HS_Code: NA; Distributor_name: NA; Distributor_part_number: NA; Footprint Path: Y:\MIS_DATABASE\Library\ALTIUM_TOOL\PCB_FOOTPRINTS\Altium_Footprint_Lib.PcbLib; Height: NA; Library Path: Y:\MIS_DATABASE\Library\ALTIUM_TOOL\SCHEMATICS_PARTS\MS_DISCRETE_Library.schlib; MECHANICAL 3D STEP FILE: NA; Manufacturer: LOCAL; Mfr_name: LOCAL; Mistral Part No: NA; Package: SMD; Project: BT MODULE_CSRBC04; RoHS: NA; Temperature: NA; Tolerance: NA; Voltage: NA; Wattage: NA; Weight: NA; Datasheet: NA
U87 U97 = TCA9517DGKR_VSSOP8: IC 2-CHANNEL BI-DIR LEVEL-SHIFTING I2C BUS REPEATER SOIC8; Chkd/date: MANIRAJA/171121; Crtd /date: ALVY/161121; Custom_Duty: 15%; Customs_HS_Code: 85423100; Distributor_name: DIGIKEY; Distributor_part_number: 296-39221-1-ND; Footprint Path: Y:\MIS_DATABASE\Library\ALTIUM_TOOL\PCB_FOOTPRINTS\Altium_Footprint_Lib.PcbLib; Height: 1.75MM; Library Path: Y:\MIS_DATABASE\Library\ALTIUM_TOOL\SCHEMATICS_PARTS\MS_MISCINTERFACE_Library.schlib; Mfr_name: TEXAS INSTRUMENTS; Mistral Part No: 141021110017-R; Package: SOIC8; Part_type: ICS\INTERFACE\LEVEL TRANSLATOR; Project: EXCITER MULTI-CH RX UNIT; RoHS: RoHS; Temperature: -40°C+85°C; Tolerance: NA; Voltage: NA; Wattage: NA; Weight: 540mg; Datasheet: Y:\MIS_DATABASE\DATASHEETS\ICS\INTERFACE\TCA9517.PDF
U120 = TPS62177_WSON10: IC 3.3V 0.5A STEP DOWN CONVERTER WITH SLEEP MODE WSON10; Chkd/date: MANIRAJA/170719; Crtd /date: MANIRAJA/170719; Custom_Duty: 15%; Customs_HS_Code: 85423100; Distributor_name: DIGIKEY; Distributor_part_number: 296-41856-1-ND; Footprint Path: Y:\MIS_DATABASE\Library\ALTIUM_TOOL\PCB_FOOTPRINTS\Altium_Footprint_Lib.PcbLib; Height: 0.80MM; Library Path: Y:\MIS_DATABASE\Library\ALTIUM_TOOL\SCHEMATICS_PARTS\MS_MISCPOWER_Library.schlib; Mfr_name: TEXAS INSTRUMENTS; Mistral Part No: 142019070007-R; Package: WSON10; Part_type: ICS\POWER\DC-DC CONVERTER; Project: TI_MAXIE_CPB; RoHS: RoHS; Temperature: -40°C+85°C; Tolerance: NA; Voltage: NA; Wattage: NA; Weight: 15mg; Datasheet: Y:\MIS_DATABASE\DATASHEETS\ICS\POWER\TPS62177.PDF
C460 = CAP: CAP CERAMIC 0.01uF 25V 10% X5R 0201; Chkd/date: MANIRAJA/230118; Crtd /date: MANIRAJA/230118; Custom_Duty: 15%; Customs_HS_Code: 85322990; Distributor_name: DIGIKEY; Distributor_part_number: GRM033R61E103KA12J-ND; Footprint Path: Y:\MIS_DATABASE\Library\ALTIUM_TOOL\PCB_FOOTPRINTS\Altium_Footprint_Lib.PcbLib; Height: 0.33MM; Library Path: Y:\MIS_DATABASE\Library\ALTIUM_TOOL\SCHEMATICS_PARTS\MS_DISCRETE_Library.schlib; Mfr_name: MURATA; Mfr_part_number: GRM033R61E103KA12J; Mistral Part No: 120018010007-R; Package: 0201; Part_type: CAPACITORS\CERAMIC; Project: TI_MAXIE_CPB; RoHS: RoHS; Temperature: -55°C+85°C; Tolerance: 10%; Voltage: 25V; Wattage: NA; Weight: 0.33mg; Datasheet: Y:\MIS_DATABASE\DATASHEETS\CAPACITORS\GRM033R61E103KA12.PDF
J16 = HEADER_2X1: CON HDR 1X2 2.54MM PITCH ST TH; Chkd/date: NAVEED/210714; Crtd /date: USMAN/031012; Custom_Duty: 24%; Customs_HS_Code: 85369090; Distributor_name: DIGIKEY; Distributor_part_number: WM8072-ND; Footprint Path: Y:\MIS_DATABASE\Library\ALTIUM_TOOL\PCB_FOOTPRINTS\Altium_Footprint_Lib.PcbLib; Height: 5.60MM; Library Path: Y:\MIS_DATABASE\Library\ALTIUM_TOOL\SCHEMATICS_PARTS\MS_CONNECTOR_Library.schlib; Mfr_name: MOLEX; Mfr_part_number: 90120-0122; Mistral Part No: 150012100005-R; Package: THRU-HOLE; Part_type: CONNECTOR\HEADERS; Project: NPOL_FEP; RoHS: RoHS; Temperature: -55°C+125°C; Tolerance: NA; Voltage: NA; Wattage: NA; Weight: 122mg; Datasheet: Y:\MIS_DATABASE\DATASHEETS\CONNECTORS\90120-XX.PDF
R185-R192 R455-R462 = RESISTOR: RES 100K 1/20W 5% 0201; Chkd/date: MANIRAJA/050517; Crtd /date: MANIRAJA/050517; Custom_Duty: 15%; Customs_HS_Code: 85332119; Distributor_name: DIGIKEY; Distributor_part_number: 311-100KNCT-ND; Footprint Path: Y:\MIS_DATABASE\Library\ALTIUM_TOOL\PCB_FOOTPRINTS\Altium_Footprint_Lib.PcbLib; Height: 0.26MM; Library Path: Y:\MIS_DATABASE\Library\ALTIUM_TOOL\SCHEMATICS_PARTS\MS_DISCRETE_Library.schlib; Mfr_name: YAGEO AMERICA; Mfr_part_number: RC0201JR-07100KL; Mistral Part No: 110009030176-R; Package: 0201; Part_type: RESISTORS\FIXED; Project: GOLDEN-I LITE; RoHS: RoHS; Temperature: -55°C+125°C; Tolerance: 5%; Voltage: NA; Wattage: 1/20W; Weight: 0.17mg; Datasheet: Y:\MIS_DATABASE\DATASHEETS\RESISTORS\RCXXXXL-SER_MAR18.PDF
R205-R220 R495 = RESISTOR: RES 1.1K 1/20W 1% 0201; Chkd/date: MANIRAJA/270721; Crtd /date: ALVY/260721; Custom_Duty: 15%; Customs_HS_Code: 85332119; Distributor_name: DIGIKEY; Distributor_part_number: YAG2474CT-ND; Footprint Path: Y:\MIS_DATABASE\Library\ALTIUM_TOOL\PCB_FOOTPRINTS\Altium_Footprint_Lib.PcbLib; Height: 0.26MM; Library Path: Y:\MIS_DATABASE\Library\ALTIUM_TOOL\SCHEMATICS_PARTS\MS_DISCRETE_Library.schlib; Mfr_name: YAGEO AMERICA; Mfr_part_number: RC0201FR-071K1L; Mistral Part No: 110009030097-R; Package: 0201; Part_type: RESISTORS\FIXED; Project: TI_AM335x SK_BRD; RoHS: RoHS; Temperature: -55°C+125°C; Tolerance: 1%; Voltage: NA; Wattage: 1/20W; Weight: 0.17mg; Datasheet: Y:\MIS_DATABASE\DATASHEETS\RESISTORS\RCXXXXL-SER_MAR18.PDF
SW2 SW3 = SW16_CHS-08A: SWITCH SLIDE SPST ST SMD; Chkd/date: MANIRAJA/051020; Crtd /date: ALVY/011020; Custom_Duty: 24%; Customs_HS_Code: 85369090; Distributor_name: DIGIKEY; Distributor_part_number: 732-3857-1-ND; Footprint Path: Y:\MIS_DATABASE\Library\ALTIUM_TOOL\PCB_FOOTPRINTS\Altium_Footprint_Lib.PcbLib; Height: 2.65MM; Library Path: Y:\MIS_DATABASE\Library\ALTIUM_TOOL\SCHEMATICS_PARTS\MS_SWITCH_Library.schlib; Mfr_name: WURTH ELECTRONICS; Mistral Part No: 130020100001-R; Package: SMD; Part_type: ELECTRO-MECHANICAL\SWITCH; Project: AM64X_SKEVM; RoHS: RoHS; Temperature: -40°C+85°C; Tolerance: NA; Voltage: NA; Wattage: NA; Weight: 281.7mg; Datasheet: Y:\MIS_DATABASE\DATASHEETS\MISC\SWITCHES\4161311608XX.PDF
U45 = SN74LVC1G08DBVRE4_SOT23-5: IC SINGLE 2-INPUT POSITIVE AND GATE SOT23-5; Chkd/date: SUHAS/221010; Crtd /date: USMAN/151008; Custom_Duty: 15%; Customs_HS_Code: 85423100; Distributor_name: DIGIKEY; Distributor_part_number: SN74LVC1G08DBVRE4-ND; Height: 1.45MM; Mfr_name: TEXAS INSTRUMENTS; Mistral Part No: 141009060026-R; Part_type: ICS\DIGITAL\GATES; Project: KHAN_MAIN; RoHS: Sb/ Br FREE; Temperature: -40°C+85°C; Datasheet: Y:\MIS_DATABASE\DATASHEETS\ICS\DIGITAL\GATES\SN74LVC1G08.PDF
U98 U101 = SN74AVC8T245RHL_QFN24: IC BUS TRANSCEIVER 8-BIT DUAL-SUPPLY QFN24; Chkd/date: VASANTHA/231216; Crtd /date: BAVISH/290411; Custom_Duty: 15%; Customs_HS_Code: 85423100; Distributor_name: DIGIKEY; Distributor_part_number: 296-17859-1-ND; Height: 1.00MM; Mfr_name: TEXAS INSTRUMENTS; Mfr_part_number: SN74AVC8T245RHLR; Mistral Part No: 143011040001-R; Package: QFN24; Part_type: ICS\TELECOM\TRANSCEIVER; Project: OMAPL1_PEC20; RoHS: RoHS; Temperature: -40°C+85°C; Tolerance: NA; Voltage: NA; Wattage: NA; Weight: NA; Datasheet: Y:\MIS_DATABASE\DATASHEETS\ICS\DIGITAL\BUSTRANSCEIVER\SN74AVC8T245.PDF
U100 = TCA6424ARGJR_QFN32: IC I2C I/O EXPANDER 24B UQFN32; Chkd/date: NAVEED/100715; Crtd /date: NAVEED/100914; Custom_Duty: 15%; Customs_HS_Code: 85423100; Distributor_name: DIGIKEY; Distributor_part_number: 296-27844-1-ND; Height: 0.60MM; Mfr_name: TEXAS INSTRUMENTS; Mistral Part No: 141014090009-R; Package: UQFN32; Part_type: ICS\DIGITAL\BUSTRANSCEIVER; Project: ZK_BIOMETRIC; RoHS: RoHS; Temperature: -40°C+85°C; Weight: NA; Datasheet: Y:\MIS_DATABASE\DATASHEETS\ICS\DIGITAL\BUSTRANSCEIVER\TCA6424AR.PDF
U18 = AM62A-EVM_SOC_FCBGA484: IC AM62A SK EVM SoC MICROPROCESSOR FCBGA484; Chkd/date: PRAVEEN/190922; Crtd /date: PRAVEEN/190922; Custom_Duty: 15%; Customs_HS_Code: 85423100; Distributor_name: NA; Distributor_part_number: NA; Footprint Path: Y:\MIS_DATABASE\Library\ALTIUM_TOOL\PCB_FOOTPRINTS\Altium_Footprint_Lib.PcbLib; Height: 2.65MM; Library Ref: AM62A-EVM_SoC_FCBGA484; Mfr_name: TEXAS INSTRUMENTS; Mistral Part No: 141220090002; Package: FCBGA484; Part_type: ICS\DIGITAL\MICROPROCESSOR; Project: TI_AM62A_SK_EVM; RoHS: NA; Temperature: NA; Tolerance: NA; Voltage: NA; Wattage: NA; Weight: NA; Datasheet: Y:\MIS_DATABASE\DATASHEETS\ICS\DIGITAL\MICROCONTROLLER\AM62A_SK_EVM.PDF

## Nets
DGND: C14.1 C15.1 C16.1 C19.2 C23.2 C24.2 C27.2 C28.2 C29.2 C133.2 C135.1 C142.2 C193.2 C194.2 C209.2 C408.2 C422.2 C437.1 C442.1 C443.2 C456.2 C457.1 C460.1 C489.2 C492.2 C500.2 C505.2 J4.1 J4.8 J4.13 J4.14 J4.19 J4.20 J4.24 J4.25 J4.32 J4.37 J4.41 J4.SH1 J4.SH2 J4.SH3 J4.SH4 J23.7 J23.16 J23.25 J23.34 J23.40 J23.41 J23.42 R36.1 R180.2 R185.2 R186.2 R187.2 R188.2 R189.2 R190.2 R191.2 R192.2 R221.1 R314.2 R455.2 R456.2 R457.2 R458.2 R459.2 R460.2 R461.2 R462.2 R471.1 R489.2 R495.1 R576.1 U7.4(GND) U42.2(GND) U45.3(GND) U87.4(GND) U97.4(GND) U98.11(GND1) U98.12(GND2) U98.13(GND3) U98.25(EP) U100.25(GND) U100.33(EP) U101.11(GND1) U101.12(GND2) U101.13(GND3) U101.25(EP) U120.1(PGND) U120.5(FB) U120.6(AGND) U120.11(EP) ; also on sheet 9 10 11 12 13 14 15 16 17 18 19 20 21 22 27 28 29 30 31 32 33 34 35 36 37 38 39 40 41 42 43
VCC1V8_CLKBUF: C14.2 C15.2 C16.2 FL1.2 R33.2 U7.6(VDD) ; also on sheet 41
VCC3V3_TA: C142.1 C408.1 C437.2 C442.2 C457.2 C460.2 C489.1 C492.1 J23.1 J23.2 J23.3 R165.1 R166.1 R205.2 R206.2 R207.2 R208.2 R209.2 R210.2 R211.2 R212.2 R213.2 R214.2 R215.2 R216.2 R217.2 R218.2 R219.2 R220.2 R410.1 R470.2 R480.2 R486.2 R490.2 R527.2 R530.2 R531.2 R543.1 R546.2 R547.2 R548.2 R559.1 R577.2 R578.2 TP88.1(TP) U45.5(VCC) U87.8(VCCB) U97.8(VCCB) U98.1(VCCA) U100.27(VCCP) U100.31(VCC) U101.1(VCCA) U120.8(SLEEP) ; also on sheet 27
VCC3V3_XDS: C135.2 R502.1 R503.1 U97.1(VCCA) ; also on sheet 27 28
VCC_3V3_MAIN: R578.1 ; also on sheet 11 12 14
VCC_3V3_SYS: C23.1 C133.1 C194.1 C422.1 C443.1 C456.1 J4.48 J4.50 R181.2 R182.2 R571.2 U42.5(VCC) U87.1(VCCA) U98.23(VCCB1) U98.24(VCCB2) U101.23(VCCB1) U101.24(VCCB2) ; also on sheet 9 10 12 13 17 18 19 21 22 28 29 30 32 33 34 35 36 37 38 39 40 41 42
VCC_5V0: C27.1 C28.1 J4.36 J4.38 ; also on sheet 9 10 32 34 37 40
VDD_1V0: C29.1 C209.1 J4.2 J4.4 ; also on sheet 10 22
VDD_2V5: C24.1 C193.1 J4.47 J4.49 ; also on sheet 10 22
VDDA_1V8: FL1.1 ; also on sheet 13 14 15
AUTO_100M_1000M_CONFIG: J4.26 ; also on sheet 39
BOOTMODE0: U101.14(B8) ; also on sheet 31
BOOTMODE1: U101.15(B7) ; also on sheet 31
BOOTMODE2: U101.16(B6) ; also on sheet 31
BOOTMODE3: U101.17(B5) ; also on sheet 31
BOOTMODE4: U101.18(B4) ; also on sheet 31
BOOTMODE5: U101.19(B3) ; also on sheet 31
BOOTMODE6: U101.20(B2) ; also on sheet 31
BOOTMODE7: U101.21(B1) ; also on sheet 31
BOOTMODE8: U98.14(B8) ; also on sheet 31
BOOTMODE9: U98.15(B7) ; also on sheet 31
BOOTMODE10: U98.16(B6) ; also on sheet 31
BOOTMODE11: U98.17(B5) ; also on sheet 31
BOOTMODE12: U98.18(B4) ; also on sheet 31
BOOTMODE13: U98.19(B3) ; also on sheet 31
BOOTMODE14: U98.20(B2) ; also on sheet 31
BOOTMODE15: U98.21(B1) ; also on sheet 31
BOOTMODE_I2C_SCL: R549.1 R559.2 TP77.1(TP) U100.29(SCL) ; also on sheet 27
BOOTMODE_I2C_SDA: R543.2 R551.1 TP86.1(TP) U100.30(SDA) ; also on sheet 27
BOOTMODEON: R221.2 U45.4(Y) U98.22(~{OE}) U101.22(~{OE})
BUF_BOOTMODE_I2C1_SCL: R503.2 U97.2(SCLA) ; also on sheet 27
BUF_BOOTMODE_I2C1_SDA: R502.2 U97.3(SDAA) ; also on sheet 27
CLKOUT0: U7.1(CLKIN) ; also on sheet 41
CPSW_ETH2_INH: J4.28 ; also on sheet 33
CPSW_ETH2_WAKE: J4.30 ; also on sheet 31
CPSW_RGMII1_ETH1_CLK: R26.2 ; also on sheet 22
CPSW_RGMII1_RD0: U18.AB16(RGMII1_RD0) ; also on sheet 22
CPSW_RGMII1_RD1: U18.V15(RGMII1_RD1) ; also on sheet 22
CPSW_RGMII1_RD2: U18.W15(RGMII1_RD2) ; also on sheet 22
CPSW_RGMII1_RD3: U18.V14(RGMII1_RD3) ; also on sheet 22
CPSW_RGMII1_RX_CTL: U18.AA15(RGMII1_RX_CTL) ; also on sheet 22
CPSW_RGMII1_RXC: U18.AA16(RGMII1_RXC) ; also on sheet 22
CPSW_RGMII1_TD0: U18.Y17(RGMII1_TD0) ; also on sheet 22
CPSW_RGMII1_TD1: U18.V16(RGMII1_TD1) ; also on sheet 22
CPSW_RGMII1_TD2: U18.Y16(RGMII1_TD2) ; also on sheet 22
CPSW_RGMII1_TD3: U18.AA17(RGMII1_TD3) ; also on sheet 22
CPSW_RGMII1_TX_CTL: U18.W16(RGMII1_TX_CTL) ; also on sheet 22
CPSW_RGMII1_TXC: R322.2 ; also on sheet 22
CPSW_RGMII2_ETH2_CLK: J4.22 R37.2
CPSW_RGMII2_RD0: J4.27 U18.AA21(RGMII2_RD0)
CPSW_RGMII2_RD1: J4.35 U18.Y20(RGMII2_RD1)
CPSW_RGMII2_RD2: J4.33 U18.AB21(RGMII2_RD2)
CPSW_RGMII2_RD3: J4.29 U18.AB20(RGMII2_RD3)
CPSW_RGMII2_RX_CTL: J4.21 U18.W18(RGMII2_RX_CTL)
CPSW_RGMII2_RXC: J4.23 U18.AA20(RGMII2_RXC)
CPSW_RGMII2_TD0: J4.15 U18.AA19(RGMII2_TD0)
CPSW_RGMII2_TD1: J4.11 U18.Y18(RGMII2_TD1)
CPSW_RGMII2_TD2: J4.9 U18.AA18(RGMII2_TD2)
CPSW_RGMII2_TD3: J4.5 U18.W17(RGMII2_TD3)
CPSW_RGMII2_TX_CTL: J4.17 U18.Y19(RGMII2_TX_CTL)
CPSW_RGMII2_TXC: J4.3 R56.2
CPSW_RGMII2_TXC_R: R56.1 U18.AB19(RGMII2_TXC)
CPSW_RGMII_INTn: J4.10 ; also on sheet 22
CPSW_RGMII_TXC_R: R322.1 U18.AB17(RGMII1_TXC)
CSI_REFCLK: R34.2 ; also on sheet 37
DIR: R480.1 U98.2(DIR) U101.2(DIR)
GPIO_CPSW2_RST: R180.1 R181.1 U42.1(A) ; also on sheet 39
IO_EXP_ADDR: R489.1 U100.26(ADDR)
PORz_OUT: R170.2 U42.3(B) ; also on sheet 19 22 41
RESETSTATz: R171.2 R178.1 ; also on sheet 18 19 20 22 37 38 39 40 41
RGMII2_BRD_CONN_DET: J4.43 R571.1 ; also on sheet 39
RGMII2_RSTn: J4.12 R314.1 U42.4(Y)
RMII_PHY_OBSCLK: J4.34 ; also on sheet 33
RMII_REF_CLOCK: J4.39 ; also on sheet 41
SoC_CLKIN: C19.1 R35.2 R36.2 ; also on sheet 33
SoC_I2C0_SCL: J4.42 ; also on sheet 9 12 21 32 41
SoC_I2C0_SDA: J4.44 ; also on sheet 9 12 21 32 41
SOC_I2C1_SCL: U87.2(SCLA) ; also on sheet 13 21 38 39 40 41
SOC_I2C1_SDA: U87.3(SDAA) ; also on sheet 13 21 38 39 40 41
SoC_I2C1_TA_SCL: R166.2 R464.1 R545.1 U87.7(SCLB)
SoC_I2C1_TA_SDA: R165.2 R466.1 R550.1 U87.6(SDAB)
SoC_RGMII_MDC: J4.16 ; also on sheet 22 31
SoC_RGMII_MDIO: J4.18 ; also on sheet 22 31
SYS_BOOTMODE0: R455.1 SW2.1 U100.1(P00) U101.10(A8)
SYS_BOOTMODE1: R456.1 SW2.2 U100.2(P01) U101.9(A7)
SYS_BOOTMODE2: R457.1 SW2.3 U100.3(P02) U101.8(A6)
SYS_BOOTMODE3: R458.1 SW2.4 U100.4(P03) U101.7(A5)
SYS_BOOTMODE4: R459.1 SW2.5 U100.5(P04) U101.6(A4)
SYS_BOOTMODE5: R460.1 SW2.6 U100.6(P05) U101.5(A3)
SYS_BOOTMODE6: R461.1 SW2.7 U100.7(P06) U101.4(A2)
SYS_BOOTMODE7: R462.1 SW2.8 U100.8(P07) U101.3(A1)
SYS_BOOTMODE8: R192.1 SW3.1 U98.10(A8) U100.9(P10)
SYS_BOOTMODE9: R191.1 SW3.2 U98.9(A7) U100.10(P11)
SYS_BOOTMODE10: R190.1 SW3.3 U98.8(A6) U100.11(P12)
SYS_BOOTMODE11: R189.1 SW3.4 U98.7(A5) U100.12(P13)
SYS_BOOTMODE12: R188.1 SW3.5 U98.6(A4) U100.13(P14)
SYS_BOOTMODE13: R187.1 SW3.6 U98.5(A3) U100.14(P15)
SYS_BOOTMODE14: R186.1 SW3.7 U98.4(A2) U100.15(P16)
SYS_BOOTMODE15: R185.1 SW3.8 U98.3(A1) U100.16(P17)
SYSBOOT_BUF_ENz: R170.1 R171.1 U45.1(A)
TCA6424_EXP_INT: R490.1 U100.32(~{INT})
TEST_GPIO1: R548.1 R556.1 ; also on sheet 27 42
TEST_GPIO2: R531.1 R533.1 ; also on sheet 27 39
TEST_GPIO3: J16.1 R486.1 R557.1 TP76.1(TP) U45.2(B) ; also on sheet 27
TEST_GPIO4: R527.1 R536.1 TP75.1(TP) U100.28(~{RESET}) ; also on sheet 27
TEST_PORZn: R547.1 R555.1 ; also on sheet 27 41
TEST_POWERDOWN: R546.1 R554.1 ; also on sheet 10 12 27
TEST_WARMRESETn: R530.1 R532.1 ; also on sheet 27 42
VMAIN: C505.1 R569.1 U120.2(VIN) ; also on sheet 9 10 11
XDS_I2C1_EN: R470.1 R471.2 U97.5(EN)
N16943223: R33.1 U7.2(1G)
N16990175: J23.27 R555.2
N16990176: J23.30 R556.2
N16990179: J23.31 R533.2
N16990180: J23.32 R557.2
N16990246: J23.26 R554.2
N16990247: J23.28 R532.2
N16990252: J23.33 R536.2
N17078351: R209.1 SW2.13
N17078353: R210.1 SW2.14
N17078355: R211.1 SW2.15
N17078357: R212.1 SW2.16
N17078758: R215.1 SW3.11
N17078760: R216.1 SW3.12
N17078762: R217.1 SW3.13
N17078764: R218.1 SW3.14
N17078766: R213.1 SW3.9
N17078768: R214.1 SW3.10
N17078770: R219.1 SW3.15
N17078778: R220.1 SW3.16
N17078974: J16.2 R495.2
N17084256: R205.1 SW2.9
N17084257: R206.1 SW2.10
N17084258: R207.1 SW2.11
N17084259: R208.1 SW2.12
N17253632: C500.1 L11.2 R563.2 R577.1 U120.10(VOS)
N17253649: L11.1 U120.9(SW)
N17253673: R563.1 TP106.1(TP) U120.7(PG)
N17253694: R569.2 U120.3(EN)
N18374804: J23.36 R545.2
N18374807: J23.37 R549.2
N18374810: J23.38 R550.2
N18374813: J23.39 R551.2
N20900570: R35.1 U7.3(Y0)
N20900572: R26.1 U7.8(Y1)
N20900574: R37.1 U7.5(Y2)
N20900809: R34.1 U7.7(Y3)
N22155496: R464.2 U97.7(SCLB)
N22155498: R466.2 U97.6(SDAB)
N22498870: R178.2 R182.1 U42.6(C)
N23398363: J4.46 TP109.1(TP)
N23398366: J4.40 TP108.1(TP)
N23696264: R410.2 R576.2 U87.5(EN)

Not connected (* = marked no-connect by the designer): J4 6* 7* 31* 45*; J23 4* 5* 6* 8* 9* 10* 11* 12* 13* 14* 15* 17* 18* 19* 20* 21* 22* 23* 24* 29* 35*; U100 17(P20)* 18(P21)* 19(P22)* 20(P23)* 21(P24)* 22(P25)* 23(P26)* 24(P27)*; U120 4(NC)*

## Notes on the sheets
sheet 23
- CPSW RGMII 2 - PHY
sheet 24
- ETHERNET PHY CLOCK BUFFER
sheet 25
- 40-PIN TEST AUTOMATION HEADER
- I2C BUS BUFFER
- Silk: AUTOMATION HDR
- TEST AUTOMATION GPIO MAPPING
- TEST AUTOMATION BOARD POWER
- SIGNAL NAME
- DESCRIPTION
- Direction WRT CTRL
- Internal/
  External
  PU/PD states
- VinMin = 4.75V
  VinMax = 24V
  Vout = 3.3V @ 0.5A
- OUTPUT
  OUTPUT
  OUTPUT
  OUTPUT
  OUTPUT
  OUTPUT
  OUTPUT
- TEST_POWERDOWN
  TEST_PORZn
  TEST_WARMRESETn
  TEST_GPIO1
  TEST_GPIO2
  TEST_GPIO3
  TEST_GPIO4
- Used to Power down the EVM
  Used to  Reset the SoC PORz
  Used to Reset the SoC Warmreset
  Used to Generate the interrupt on
  SOC_GPIO1_23 Pin
  Connected to IO Expander to Communicate with SOC
  Used to Enable the BOOTMODE Buffer
  Used to Reset the Bootmode I2C IO Expander
- External Pullup
  External Pullup
  External Pullup
  External Pullup
  External Pullup
  External Pullup
  External Pullup
- For Automotive grade:
  L11 replace with LQH32PZ100MNC
- SILK SCREEN :  VCC3V3_TA
- Normal Mode SLEEP = HIGH
  Sleep Mode SLEEP = LOW
sheet 26
- BOOT MODE BUFFERS
- BOOTMODE IO EXPANDER
- DIR = H: A -> B
  DIR = L: B -> A
  OE = H: output = Hi-Z
- DIR = H: A -> B
  DIR = L: B -> A
  OE = H: output = Hi-Z
- I2C ADDRESS: 0x22
- BOOT MODE SWITCHES
- BOOT MODES SUPPORTED
- SWITCH ON  =  LOGIC 1
  SWITCH OFF =  LOGIC 0
- 1. OSPI
- 2. MMC1 - SD CARD
- Silk: BMODE 0-7
- Silk: BMODE 8-15
- 3. UART
- 4. eMMC
- 5. ETHERNET
- 6. USB0 DFU
- 7. USB0 MS
